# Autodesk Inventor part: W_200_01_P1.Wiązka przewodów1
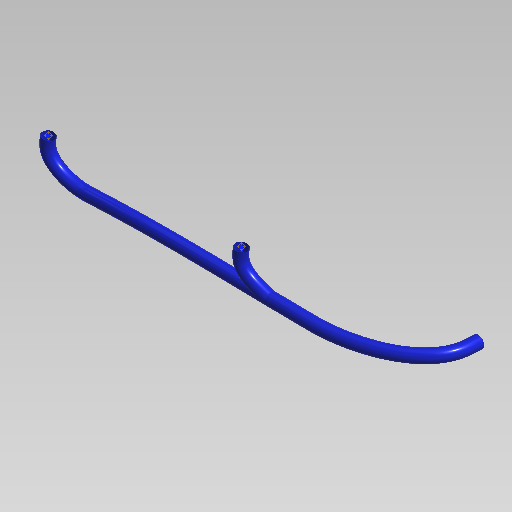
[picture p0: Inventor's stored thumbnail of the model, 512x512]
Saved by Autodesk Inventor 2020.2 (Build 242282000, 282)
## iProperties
GlobalPropertyList: <PropertyList/>
Manager: www.cadconsulting.pl
Company: Fabian Stasiak CAD Consulting
Created: 2014-09
Part Number: W_200_01_P1.Wiązka przewodów1
Material: Ogólne
Document SubType Name: Modelowanie
Designer: F.Stasiak
Appearance: Ogólne
Catalog Web Link: www.expertbooks.pl
Author: F.Stasiak
Subject: Zbiór ćwiczeń. Autodesk Inventor 2020. Kurs Professional
## Parameters: d2 = 0, d3 = 0, d4 = 0, d5 = 0, d6 = 0, d7 = 0
